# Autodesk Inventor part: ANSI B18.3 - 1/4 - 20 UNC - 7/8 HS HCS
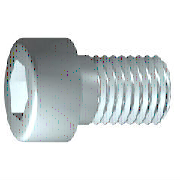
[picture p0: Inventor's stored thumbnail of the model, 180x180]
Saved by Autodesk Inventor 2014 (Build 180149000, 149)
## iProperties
IsCustomPart: 0
Created: 2008-01
Part Number: ANSI B18.3 - 1/4 - 20 UNC - 7/8 HS HCS
Material: Steel, Mild
Description: Hexagon Socket Head Cap Screw
Document SubType Name: Modeling
Standard: ANSI B18.3
Designer: latalom
Standard Revision: 2003
Standards Organization: ANSI
Language: en-US
Size Designation: 1/4 - 20 UNC - 7/8
Categories: <MemberInstance><Categories><Category DisplayName="Fasteners" InternalName="e4da775c-781d-43d5-af7c-5136215cf5a6" Mnemonic="FSTN"><Category DisplayName="Bolts"
Density: 7.86 g/cm^3
Mass: 8.45886 g
Surface Area: 8.12272 cm^2
Volume: 1.07619 cm^3
Appearance: Steel
Author: latalom
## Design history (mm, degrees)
sketch "Sketch1"
  geometry: L1 (-1.71, 0)-(22.225, 0); L2 (22.225, 0)-(22.225, 3.175); L3 (22.225, 3.175)-(3.175, 3.175); L4 (3.175, 3.175)-(0, 3.175); L5 (0, 3.175)-(0, 3.175); L6 (0, 3.175)-(0, 4.763); L7 (0, 4.763)-(-6.35, 4.763); L8 (-6.35, 4.763)-(-6.35, 2.757); L9 (-6.35, 2.757)-(-3.302, 2.757); L10 (-3.302, 2.757)-(-1.71, 0); L11 (-12.065, 0)-(27.94, 0) reference; L12 (0, -0.953)-(0, 5.715) reference; L13 (3.175, 3.175)-(0, 3.175)
  constraints: 22 end point, 6 parallel, 2 collinear, 2 perpendicular, 1 horizontal, 1 point on line
  dimensions: "d1" = 19.0498 distance from line of L3.end L2 (= GEL); "d2" = 3.1751 distance of L4.end L3.end (computed from GAL); "d3" = 6.35 distance between parallel lines of L8 L6 (= KOH); "d4" = 3.048 distance of L8.end L9.end (= INTI); "d5" = 60 deg angle of L10 L1; "d6" = 6.35 diameter of L3 L1 (= GD); "d7" = 6.35 diameter of L5 L1 (= BDM); "d8" = 5.51393 diameter of L9 L1 (= 1.1547 x SW); "d9" = 9.525 diameter of L7 L1 (= KOD); "d26" = 22.225 distance between parallel lines of L12 L2 (= NLG)
revolve "Body" sketch "Sketch1" stored, may be unused: angle "d10" = 90 deg
sketch "Sketch2"
  geometry: L1 (0, -6.668)-(0, 6.668) reference; L2 (-6.668, 0)-(6.668, 0) reference; L3 (2.757, 0)-(1.378, -2.388); L4 (1.378, -2.388)-(-1.378, -2.388); L5 (-1.378, -2.388)-(-2.757, 0); L6 (-2.757, 0)-(-1.378, 2.388); L7 (-1.378, 2.388)-(1.378, 2.388); L8 (1.378, 2.388)-(2.757, 0); 2 further points
  constraints: 12 end point, 1 coincident, 1 horizontal alignment, 1 point on line, 12 other
extrude "Slot" join sketch "Sketch2" stored distance "d11" = 10; taper "d12" = 0 deg
workplane "Work Plane1"
fillet "Fillet2" dims "d30" = 0.1778 (= R)
body "Solid1"
fillet "Fillet1" dims "d17" = 0.635 (= RR)
feature "Thread" dims "d13" = 19.0498 (= GEL), "d14" = 0
chamfer "Chamfer1" distance "d15" = 0.75565 (= -0.5 x SPD + 0.5 x GD); stored, may be unused: second distance "d16" = 0.75565 (= GUL), angle "d27" = 45 deg
other parameters: "GD" = 6.35 (= KOH) [user parameter; used in 2 equation terms], "NLG" = 22.225 [user parameter; used in 1 equation term], "GEL" = 19.0498 [user parameter; used in 2 equation terms], "KOD" = 9.525 [user parameter; used in 1 equation term], "KOH" = 6.35 [user parameter; used in 3 equation terms], "INTI" = 3.048 [user parameter; used in 1 equation term], "GAL" = 3.175 [user parameter; used in 1 equation term], "GUL" = 0.75565 [user parameter; used in 1 equation term], "BDM" = 6.35 (= KOH) [user parameter; used in 1 equation term], "SW" = 4.7752 [user parameter; used in 2 equation terms], "RR" = 0.635 [user parameter; used in 1 equation term], "SPD" = 4.8387 [user parameter; used in 2 equation terms], "d19" = 0, "d28" = 0, "d29" = 0, "R" = 0.1778 [user parameter; used in 1 equation term], "PHH" = 0.2032 [user parameter], "GD1" = 4.8387 (= SPD) [user parameter], "THREADDIA" = 6.35 [user parameter], "FAWI" = 45 deg [user parameter], "PTC" = 1.27 (computed from TPU) [user parameter], "KOH1" = 5.715 [user parameter], "NND" = 6.35 [user parameter], "TOA" = 30 deg [user parameter], "E0" = 5.51536 (= 1.155 x SW) [user parameter]
